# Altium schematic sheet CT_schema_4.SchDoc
size 293 x 156 mm
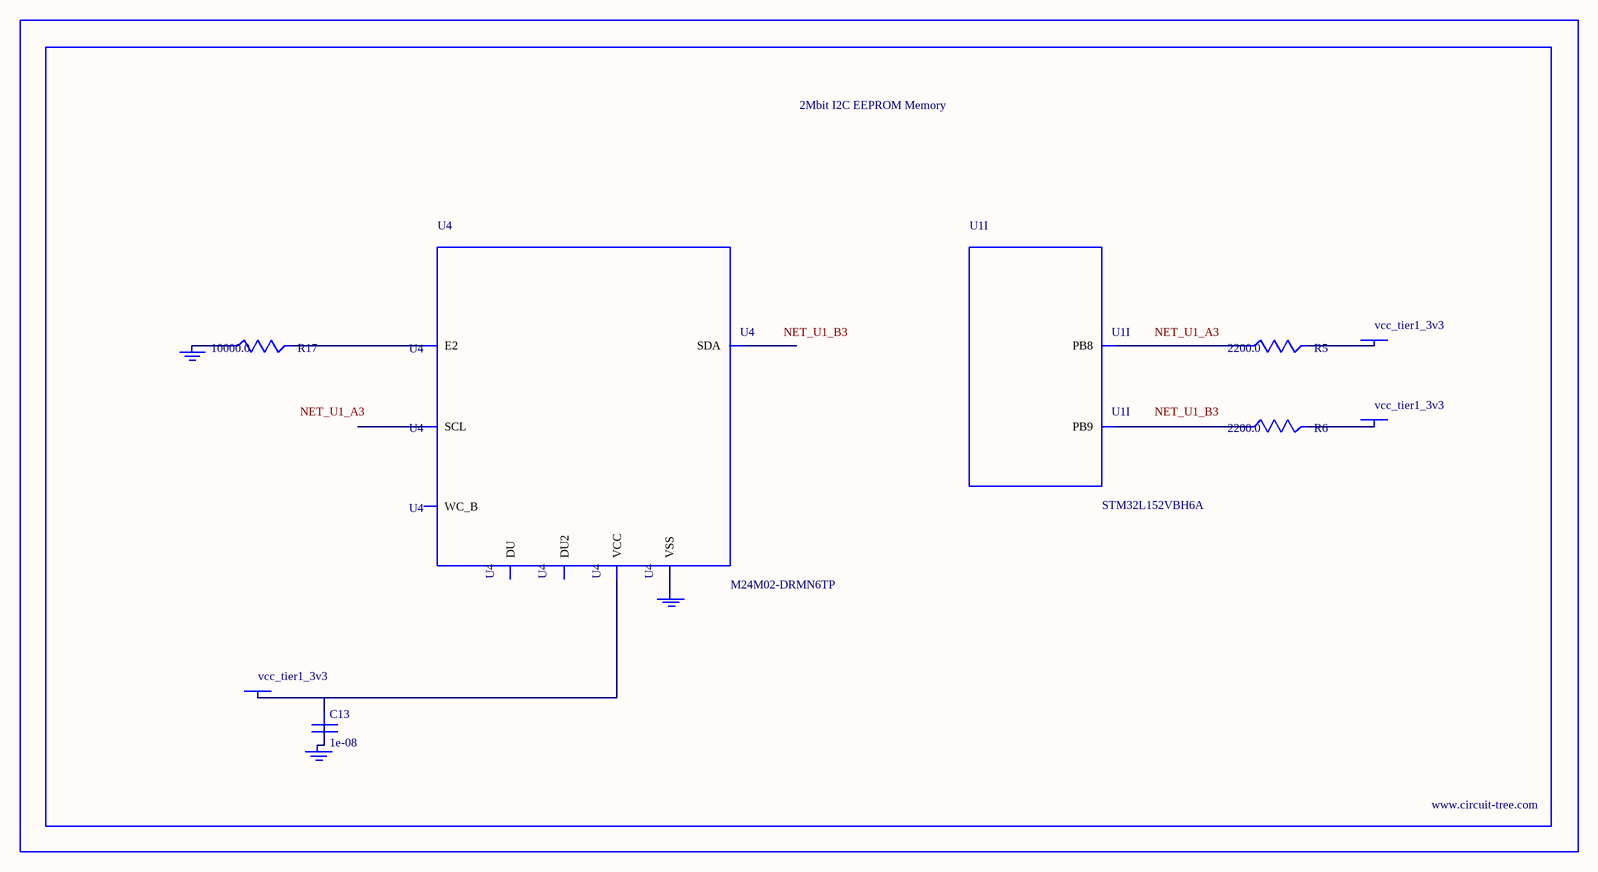
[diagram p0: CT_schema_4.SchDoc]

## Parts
BORDER3  (no value)
C13  1e-08  [C0402]
GND_INSTANCE_3_0  (no value)
GND_INSTANCE_3_1  (no value)
GND_INSTANCE_3_2  (no value)
POWER_INSTANCE_3_0  vcc_tier1_3v3
POWER_INSTANCE_3_1  vcc_tier1_3v3
POWER_INSTANCE_3_2  vcc_tier1_3v3
R5  2200.0  [R0603]
R6  2200.0  [R0603]
R17  10000.0  [R0603]
U1  STM32L152VBH6A  [UFBGA100]  (part I of 9)
U4  M24M02-DRMN6TP  [SOIC-8]

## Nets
NetC13_1: C13.1 POWER_INSTANCE_3_0.0(PWR) U4.8(VCC)
NetC13_2: C13.2 GND_INSTANCE_3_1.0(GND)
NetGND_INSTANCE_3_0_0: GND_INSTANCE_3_0.0(GND) R17.1
NetGND_INSTANCE_3_2_0: GND_INSTANCE_3_2.0(GND) U4.4(VSS)
NetPOWER_INSTANCE_3_1_0: POWER_INSTANCE_3_1.0(PWR) R5.2
NetPOWER_INSTANCE_3_2_0: POWER_INSTANCE_3_2.0(PWR) R6.2
NetR5_1: R5.1 U1.A3(PB8)
NetR6_1: R6.1 U1.B3(PB9)
NetR17_2: R17.2 U4.3(E2)

Not connected (* = marked no-connect by the designer): U4 1(DU) 2(DU2) 5(SDA) 6(SCL) 7(WC_B)

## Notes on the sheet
- Labels drawn without touching a wire or pin: NET_U1_A3, NET_U1_B3

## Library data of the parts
BORDER3 = BORDER_PAGE3
C13 = C0402C103K3RAC
GND_INSTANCE_3_0-GND_INSTANCE_3_2 = GND
POWER_INSTANCE_3_0-POWER_INSTANCE_3_2 = PWR
R5 R6 = RC0603JR-072K2L
R17 = RC0603JR-0710KL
